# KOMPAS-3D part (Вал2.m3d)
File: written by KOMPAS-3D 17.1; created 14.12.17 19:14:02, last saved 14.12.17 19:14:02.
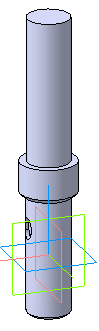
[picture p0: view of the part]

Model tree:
1. Операция без истории:1  (labels: Вал2)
